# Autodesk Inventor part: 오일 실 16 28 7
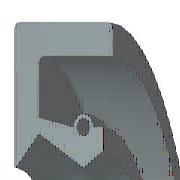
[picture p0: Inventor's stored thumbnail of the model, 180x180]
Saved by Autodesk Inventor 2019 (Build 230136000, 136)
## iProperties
Created: 2012-02
Part Number: 오일 실 16 28 7
Material: 고무
Description: 오일-실
Document SubType Name: Modeling
Standard: KS B 2804
Designer: mduedu
Standards Organization: KS
Language: ko-KR
Size Designation: D - 16 28 7
Categories: <MemberInstance><Categories><Category DisplayName="샤프트 부품" InternalName="7f7aeb1f-a693-4053-b835-cee3144e0d98" Mnemonic="SHFT"><Category DisplayName="실링" Intern
Density: 0.93 g/cm^3
Appearance: 고무 - 검은색 - 버전 1.1
IsCustomPart: 1
Author: mduedu
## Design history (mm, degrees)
revolve "본체" stored, may be unused: angle "d17" = 90 deg
revolve "스프링1" stored, may be unused: angle "d18" = 90 deg
fillet "모깎기3" dims "d43" = 0.5
body "Solid1"
sketch "스케치1"
  geometry: L1 (0, 14)-(7, 14); L2 (7, 12.25)-(1.75, 12.25); L3 (1.75, 9.75)-(4.9, 8); L4 (4.9, 8)-(0, 8); L5 (0, 0)-(9.586, 0) reference; L6 (4.9, 8)-(6.3, 8.875); L7 (0, 18)-(0, -3) reference; L8 (-1.941, 0)-(11.507, 0) reference; L9 (4.2, 10.1)-(1.75, 10.59); L10 (1.75, 10.59)-(1.75, 12.25); L11 (0, 14)-(0, 8.088); L12 (4.9, 8)-(0, 8); L13 (1.75, 9.75)-(0.152, 8.028); L14 (7, 14)-(7, 12.25); L15 (5.6, 10.1)-(6.3, 10.1); L16 (6.3, 10.1)-(6.3, 8.875); C1 r 0.455 at (4.9, 10.1); A1 r 0.7 centre (4.9, 10.1) between (5.6, 10.1) and (4.2, 10.1); A2 r 0.088 centre (0.088, 8.088) between (0, 8.088) and (0.152, 8.028); 1 further point
  constraints: 28 end point, 5 horizontal alignment, 5 point on line, 4 point on circle, 4 vertical alignment, 3 centre point, 3 tangent, 2 collinear, 2 horizontal, 2 perpendicular, 1 coincident, 1 parallel
  dimensions: "d0" = 28 diameter of L1 L5 (= SD2); "d1" = 1.75 distance of L1.end L2.start (= SD); "d2" = 0.91 diameter of C1 (= SPDI); "d3" = 1.4 diameter of A1 (= SPDA); "d4" = 16 diameter of L3.end L5 (= NND); "d5" = 19.5 diameter of L3.start L5 (= TKDM); "d7" = 21.18 diameter of L9.end L5 (= TKDM + 0.24 x SWDT); "d8" = 1.75 distance between parallel lines of L11 L10 (= SD); "d9" = 4.9 distance from line of L11 C1.centre (= SPDST); "d10" = 20.2 diameter of C1.centre L5 (= HLDM); "d11" = 0.0875 radius of A2 (= 0.25 x LAB); "d12" = 6.3 distance between parallel lines of L11 L16 (= SDI); "d13" = 17.75 diameter of L6.end L5 (= ABDM); "d14" = 7 distance from line of L11 L1.end (= SWDT)
fillet "모깎기1" dims "d6" = 0.3 (= RR)
other parameters: "SD2" = 28 [user parameter; used in 1 equation term], "SWDT" = 7 [user parameter; used in 2 equation terms], "RR" = 0.3 [user parameter; used in 1 equation term], "SD" = 1.75 [user parameter; used in 2 equation terms], "NND" = 16 [user parameter; used in 1 equation term], "SPDA" = 1.4 [user parameter; used in 1 equation term], "SPDI" = 0.91 [user parameter; used in 1 equation term], "TKDM" = 19.5 [user parameter; used in 2 equation terms], "HLDM" = 20.2 [user parameter; used in 1 equation term], "ABDM" = 17.75 [user parameter; used in 1 equation term], "SDI" = 6.3 [user parameter; used in 1 equation term], "SPDST" = 4.9 [user parameter; used in 1 equation term], "LAB" = 0.35 [user parameter; used in 1 equation term], "d15" = 0, "d16" = 0, "d19" = 0
